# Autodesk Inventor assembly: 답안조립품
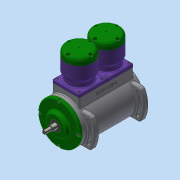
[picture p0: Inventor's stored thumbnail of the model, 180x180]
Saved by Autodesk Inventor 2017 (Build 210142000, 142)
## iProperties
Part Number: 답안조립품
Material: 일반
Document SubType Name: Assembly
Designer: Administrator
Author: Administrator
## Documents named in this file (16)
- C:\Users\Administrator\Desktop\620106V1011\답안조립품.iam
- C:\Users\Administrator\Desktop\620106V1011\본체.ipt
- C:\Users\Administrator\Desktop\620106V1011\크랭크축.ipt
- C:\Users\Administrator\Desktop\620106V1011\베어링 6303.ipt
- C:\Users\Administrator\Desktop\620106V1011\앞커버.ipt
- C:\Users\Administrator\Desktop\620106V1011\오일 실 17 x 32 x 8.ipt
- C:\Users\Administrator\Desktop\620106V1011\볼트 M4 x 12.ipt
- C:\Users\Administrator\Desktop\620106V1011\실린더.ipt
- C:\Users\Administrator\Desktop\620106V1011\실린더헤드.ipt
- C:\Users\Administrator\Desktop\620106V1011\볼트 M5 x 20.ipt
- C:\Users\Administrator\Desktop\620106V1011\커넥팅로드.ipt
- C:\Users\Administrator\Desktop\620106V1011\커넥팅로드 엔드.ipt
- C:\Users\Administrator\Desktop\620106V1011\육각 머리 볼트 M4 x 16.ipt
- C:\Users\Administrator\Desktop\620106V1011\너트 M4.ipt
- C:\Users\Administrator\Desktop\620106V1011\피스톤.ipt
- C:\Users\Administrator\Desktop\620106V1011\피스톤핀.ipt
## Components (4 placed, 2 different names)
1. 피스톤:1
2. 피스톤핀:1
3. 피스톤:2
4. 피스톤핀:2
